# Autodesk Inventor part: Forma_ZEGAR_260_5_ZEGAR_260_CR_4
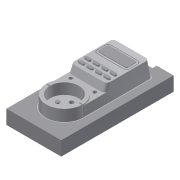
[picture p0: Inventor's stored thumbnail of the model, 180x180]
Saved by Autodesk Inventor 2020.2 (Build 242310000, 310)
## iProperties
Created: 2015-01
Part Number: Forma_ZEGAR_260_5_ZEGAR_260_CR_4
Material: Ogólny
Document SubType Name: Modeling
Designer: F.Stasiak
Density: 1 g/cm^3
Appearance: Domyślna
Catalog Web Link: www.expertbooks.pl
Manager: www.cadconsulting.pl
Company: Fabian Stasiak CAD Consulting
Author: F.Stasiak
Subject: Zbiór ćwiczeń. Autodesk Inventor 2020. Kurs Professional
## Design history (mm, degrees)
node "Forma_ZEGAR_260_4_ZEGAR_260_CR_Base"
feature "Bryła1::Forma_ZEGAR_260_4_ZEGAR_260_CR_Base"
tag "Bryła wyprowadzona1"
node "Bryła1"
feature "Forma_ZEGAR_260_4_ZEGAR_260_CR_Base_Bodies"
